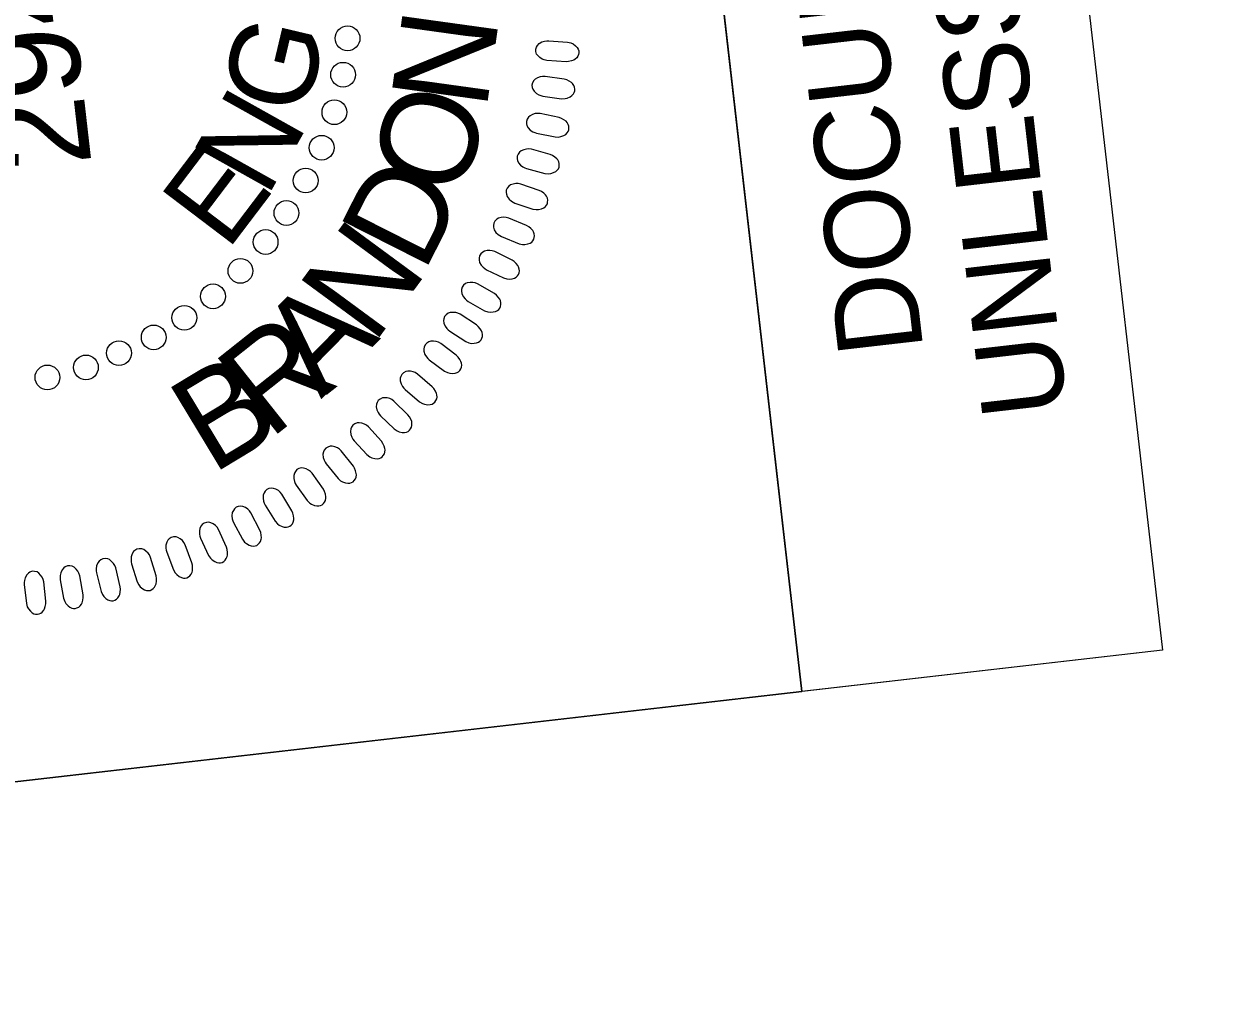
# Model space of a CAD drawing. Extents: x 474105 to 475385, y 502977 to 504774.
# Drawn here: x 474251.2 to 474328.5, y 504432.7 to 504496.5 of the extents above; entities that cross this region are included whole.
import ezdxf

# ---------------------------------------------------------------- set-up
doc = ezdxf.new("R2010")
doc.units = 0
for name, color, linetype in [('Sheet Layout Plan Border', 7, 'Continuous'), ('Sheet PE Seal Cell', 7, 'Continuous'), ('Sheet Plan CELL', 7, 'Continuous'), ('Sheet Sticker Exception Certification CELL', 7, 'Continuous')]:
    doc.layers.add(name, color=color, linetype=linetype)

msp = doc.modelspace()

# ---------------------------------------------------------------- linework, layer by layer
at = {"layer": 'Sheet Layout Plan Border'}
msp.add_lwpolyline([(475344.023, 503264.528), (475192.283, 504585.291), (475112.79, 504576.158), (474903.647, 504485.248), (474306.118, 504619.674), (474302.093, 504654.703), (474324.925, 504455.973), (474152.509, 504436.164), (474168.763, 504438.032), (474279.778, 503999.559), (474242.045, 503987.592), (474254.812, 503913.596), (474216.701, 503877.461), (474300.887, 503144.66)], close=True, dxfattribs=at)
at = {"layer": 'Sheet PE Seal Cell'}
for points in [[(474285.189, 504495.424), (474286.413, 504495.333), (474286.628, 504495.279), (474286.764, 504495.217), (474286.925, 504495.092), (474287.027, 504494.987), (474287.098, 504494.87), (474287.13, 504494.762), (474287.141, 504494.649), (474287.113, 504494.539), (474287.074, 504494.422), (474287.007, 504494.322), (474286.9, 504494.225), (474286.816, 504494.171), (474286.662, 504494.115), (474286.478, 504494.069), (474286.317, 504494.058), (474285.064, 504494.145), (474284.896, 504494.179), (474284.76, 504494.235), (474284.608, 504494.336), (474284.477, 504494.458), (474284.404, 504494.561), (474284.357, 504494.721), (474284.348, 504494.873), (474284.399, 504495.018), (474284.457, 504495.119), (474284.565, 504495.239), (474284.743, 504495.345), (474284.927, 504495.399), (474285.058, 504495.419)], [(474284.808, 504491.836), (474286.024, 504491.667), (474286.245, 504491.675), (474286.392, 504491.707), (474286.575, 504491.795), (474286.697, 504491.876), (474286.791, 504491.977), (474286.845, 504492.074), (474286.88, 504492.183), (474286.875, 504492.296), (474286.862, 504492.42), (474286.818, 504492.531), (474286.733, 504492.648), (474286.663, 504492.719), (474286.523, 504492.805), (474286.353, 504492.889), (474286.198, 504492.933), (474284.955, 504493.113), (474284.784, 504493.114), (474284.639, 504493.088), (474284.469, 504493.021), (474284.315, 504492.93), (474284.223, 504492.844), (474284.142, 504492.697), (474284.102, 504492.552), (474284.121, 504492.397), (474284.157, 504492.287), (474284.238, 504492.148), (474284.389, 504492.006), (474284.558, 504491.915), (474284.682, 504491.868)], [(474284.406, 504489.441), (474285.609, 504489.197), (474285.831, 504489.19), (474285.978, 504489.213), (474286.167, 504489.289), (474286.294, 504489.363), (474286.394, 504489.458), (474286.454, 504489.551), (474286.496, 504489.658), (474286.498, 504489.772), (474286.493, 504489.895), (474286.456, 504490.009), (474286.378, 504490.132), (474286.312, 504490.206), (474286.178, 504490.302), (474286.014, 504490.396), (474285.863, 504490.45), (474284.633, 504490.707), (474284.462, 504490.719), (474284.316, 504490.702), (474284.142, 504490.646), (474283.983, 504490.564), (474283.885, 504490.484), (474283.795, 504490.343), (474283.746, 504490.2), (474283.755, 504490.045), (474283.784, 504489.933), (474283.856, 504489.789), (474283.998, 504489.638), (474284.162, 504489.536), (474284.282, 504489.481)], [(474283.762, 504487.144), (474284.947, 504486.825), (474285.168, 504486.804), (474285.317, 504486.818), (474285.51, 504486.882), (474285.641, 504486.947), (474285.747, 504487.035), (474285.813, 504487.126), (474285.861, 504487.229), (474285.871, 504487.342), (474285.873, 504487.466), (474285.843, 504487.582), (474285.773, 504487.709), (474285.712, 504487.788), (474285.585, 504487.891), (474285.427, 504487.996), (474285.279, 504488.059), (474284.067, 504488.393), (474283.898, 504488.416), (474283.752, 504488.408), (474283.574, 504488.363), (474283.41, 504488.291), (474283.308, 504488.218), (474283.209, 504488.082), (474283.151, 504487.942), (474283.151, 504487.788), (474283.172, 504487.674), (474283.235, 504487.525), (474283.368, 504487.366), (474283.524, 504487.254), (474283.641, 504487.192)], [(474283.003, 504484.915), (474284.165, 504484.523), (474284.385, 504484.488), (474284.534, 504484.492), (474284.731, 504484.544), (474284.866, 504484.601), (474284.977, 504484.682), (474285.049, 504484.768), (474285.103, 504484.869), (474285.12, 504484.981), (474285.13, 504485.104), (474285.107, 504485.222), (474285.046, 504485.353), (474284.99, 504485.436), (474284.87, 504485.547), (474284.719, 504485.662), (474284.575, 504485.734), (474283.387, 504486.143), (474283.218, 504486.176), (474283.072, 504486.177), (474282.892, 504486.144), (474282.724, 504486.083), (474282.617, 504486.016), (474282.51, 504485.886), (474282.443, 504485.751), (474282.433, 504485.597), (474282.447, 504485.481), (474282.501, 504485.329), (474282.623, 504485.162), (474282.772, 504485.041), (474282.885, 504484.971)], [(474282.139, 504482.743), (474283.274, 504482.278), (474283.491, 504482.23), (474283.641, 504482.225), (474283.84, 504482.264), (474283.979, 504482.313), (474284.095, 504482.386), (474284.171, 504482.468), (474284.232, 504482.565), (474284.256, 504482.675), (474284.274, 504482.797), (474284.259, 504482.917), (474284.205, 504483.052), (474284.155, 504483.137), (474284.041, 504483.256), (474283.898, 504483.38), (474283.759, 504483.461), (474282.599, 504483.944), (474282.433, 504483.987), (474282.287, 504483.998), (474282.105, 504483.976), (474281.934, 504483.926), (474281.823, 504483.866), (474281.708, 504483.743), (474281.633, 504483.612), (474281.613, 504483.459), (474281.62, 504483.343), (474281.664, 504483.187), (474281.776, 504483.013), (474281.916, 504482.882), (474282.024, 504482.806)], [(474281.162, 504480.599), (474282.266, 504480.064), (474282.48, 504480.002), (474282.628, 504479.988), (474282.83, 504480.015), (474282.97, 504480.055), (474283.091, 504480.121), (474283.173, 504480.197), (474283.239, 504480.29), (474283.271, 504480.399), (474283.296, 504480.52), (474283.288, 504480.64), (474283.244, 504480.778), (474283.198, 504480.867), (474283.093, 504480.992), (474282.957, 504481.124), (474282.824, 504481.214), (474281.696, 504481.769), (474281.534, 504481.823), (474281.388, 504481.843), (474281.206, 504481.832), (474281.031, 504481.792), (474280.917, 504481.739), (474280.794, 504481.625), (474280.712, 504481.499), (474280.683, 504481.346), (474280.681, 504481.23), (474280.715, 504481.073), (474280.816, 504480.892), (474280.948, 504480.752), (474281.052, 504480.669)], [(474279.975, 504478.549), (474281.043, 504477.945), (474281.252, 504477.87), (474281.4, 504477.847), (474281.603, 504477.861), (474281.746, 504477.892), (474281.871, 504477.95), (474281.957, 504478.021), (474282.03, 504478.109), (474282.067, 504478.217), (474282.1, 504478.336), (474282.1, 504478.456), (474282.064, 504478.597), (474282.024, 504478.688), (474281.926, 504478.82), (474281.8, 504478.96), (474281.672, 504479.058), (474280.582, 504479.683), (474280.423, 504479.747), (474280.279, 504479.776), (474280.097, 504479.777), (474279.919, 504479.748), (474279.803, 504479.703), (474279.673, 504479.596), (474279.582, 504479.475), (474279.543, 504479.325), (474279.536, 504479.209), (474279.559, 504479.05), (474279.649, 504478.863), (474279.772, 504478.715), (474279.87, 504478.625)], [(474278.787, 504476.62), (474279.815, 504475.95), (474280.019, 504475.862), (474280.165, 504475.829), (474280.368, 504475.831), (474280.513, 504475.853), (474280.641, 504475.903), (474280.732, 504475.969), (474280.81, 504476.052), (474280.854, 504476.156), (474280.894, 504476.273), (474280.901, 504476.393), (474280.874, 504476.536), (474280.841, 504476.63), (474280.752, 504476.767), (474280.634, 504476.915), (474280.513, 504477.021), (474279.463, 504477.713), (474279.309, 504477.787), (474279.167, 504477.825), (474278.985, 504477.837), (474278.807, 504477.82), (474278.686, 504477.782), (474278.551, 504477.683), (474278.453, 504477.568), (474278.405, 504477.421), (474278.39, 504477.306), (474278.404, 504477.145), (474278.481, 504476.953), (474278.594, 504476.797), (474278.687, 504476.703)], [(474277.459, 504474.766), (474278.444, 504474.033), (474278.642, 504473.932), (474278.785, 504473.891), (474278.988, 504473.88), (474279.135, 504473.892), (474279.265, 504473.934), (474279.359, 504473.994), (474279.442, 504474.073), (474279.493, 504474.174), (474279.541, 504474.289), (474279.556, 504474.408), (474279.537, 504474.551), (474279.51, 504474.647), (474279.43, 504474.791), (474279.321, 504474.945), (474279.207, 504475.059), (474278.203, 504475.815), (474278.054, 504475.898), (474277.915, 504475.945), (474277.734, 504475.969), (474277.555, 504475.962), (474277.433, 504475.932), (474277.291, 504475.842), (474277.185, 504475.733), (474277.128, 504475.59), (474277.106, 504475.476), (474277.11, 504475.315), (474277.175, 504475.118), (474277.279, 504474.956), (474277.365, 504474.855)], [(474275.891, 504472.839), (474276.827, 504472.046), (474277.018, 504471.933), (474277.159, 504471.882), (474277.361, 504471.858), (474277.507, 504471.862), (474277.641, 504471.896), (474277.739, 504471.95), (474277.826, 504472.022), (474277.884, 504472.121), (474277.938, 504472.232), (474277.96, 504472.35), (474277.951, 504472.494), (474277.929, 504472.591), (474277.859, 504472.74), (474277.76, 504472.901), (474277.654, 504473.021), (474276.699, 504473.839), (474276.555, 504473.932), (474276.419, 504473.987), (474276.24, 504474.023), (474276.061, 504474.027), (474275.938, 504474.004), (474275.79, 504473.924), (474275.678, 504473.822), (474275.612, 504473.682), (474275.583, 504473.57), (474275.576, 504473.409), (474275.629, 504473.208), (474275.722, 504473.04), (474275.802, 504472.934)], [(474274.304, 504471.137), (474275.189, 504470.286), (474275.373, 504470.162), (474275.51, 504470.102), (474275.71, 504470.066), (474275.856, 504470.059), (474275.991, 504470.085), (474276.092, 504470.133), (474276.185, 504470.2), (474276.248, 504470.295), (474276.309, 504470.402), (474276.339, 504470.518), (474276.339, 504470.663), (474276.323, 504470.762), (474276.262, 504470.914), (474276.174, 504471.081), (474276.075, 504471.208), (474275.173, 504472.085), (474275.036, 504472.186), (474274.904, 504472.25), (474274.727, 504472.295), (474274.548, 504472.312), (474274.424, 504472.297), (474274.272, 504472.225), (474274.154, 504472.131), (474274.079, 504471.996), (474274.043, 504471.886), (474274.026, 504471.725), (474274.065, 504471.522), (474274.148, 504471.348), (474274.221, 504471.237)], [(474272.595, 504469.528), (474273.425, 504468.623), (474273.601, 504468.487), (474273.733, 504468.419), (474273.931, 504468.37), (474274.077, 504468.355), (474274.213, 504468.373), (474274.317, 504468.414), (474274.414, 504468.475), (474274.482, 504468.565), (474274.55, 504468.668), (474274.587, 504468.783), (474274.597, 504468.927), (474274.587, 504469.027), (474274.535, 504469.182), (474274.458, 504469.355), (474274.367, 504469.488), (474273.523, 504470.418), (474273.391, 504470.528), (474273.264, 504470.601), (474273.09, 504470.658), (474272.914, 504470.685), (474272.788, 504470.678), (474272.631, 504470.616), (474272.508, 504470.529), (474272.425, 504470.399), (474272.381, 504470.292), (474272.355, 504470.132), (474272.382, 504469.927), (474272.453, 504469.748), (474272.519, 504469.633)], [(474270.779, 504468.034), (474271.55, 504467.08), (474271.717, 504466.932), (474271.845, 504466.857), (474272.039, 504466.795), (474272.183, 504466.771), (474272.321, 504466.779), (474272.427, 504466.814), (474272.527, 504466.869), (474272.602, 504466.956), (474272.676, 504467.054), (474272.72, 504467.166), (474272.739, 504467.309), (474272.735, 504467.409), (474272.693, 504467.568), (474272.627, 504467.745), (474272.544, 504467.883), (474271.76, 504468.865), (474271.637, 504468.983), (474271.513, 504469.063), (474271.344, 504469.131), (474271.169, 504469.169), (474271.043, 504469.17), (474270.883, 504469.118), (474270.754, 504469.039), (474270.663, 504468.915), (474270.613, 504468.81), (474270.577, 504468.652), (474270.59, 504468.446), (474270.651, 504468.263), (474270.709, 504468.144)], [(474268.85, 504466.649), (474269.56, 504465.647), (474269.717, 504465.491), (474269.84, 504465.407), (474270.029, 504465.333), (474270.173, 504465.3), (474270.31, 504465.3), (474270.418, 504465.327), (474270.522, 504465.376), (474270.601, 504465.457), (474270.681, 504465.551), (474270.732, 504465.66), (474270.76, 504465.802), (474270.763, 504465.902), (474270.731, 504466.063), (474270.676, 504466.244), (474270.603, 504466.387), (474269.882, 504467.417), (474269.765, 504467.542), (474269.647, 504467.629), (474269.482, 504467.708), (474269.31, 504467.757), (474269.184, 504467.766), (474269.022, 504467.724), (474268.888, 504467.653), (474268.79, 504467.534), (474268.733, 504467.433), (474268.687, 504467.279), (474268.688, 504467.071), (474268.736, 504466.885), (474268.787, 504466.763)], [(474266.835, 504465.363), (474267.48, 504464.319), (474267.627, 504464.152), (474267.745, 504464.061), (474267.93, 504463.976), (474268.07, 504463.934), (474268.208, 504463.925), (474268.317, 504463.946), (474268.423, 504463.988), (474268.508, 504464.064), (474268.594, 504464.153), (474268.652, 504464.258), (474268.688, 504464.398), (474268.697, 504464.497), (474268.676, 504464.66), (474268.632, 504464.844), (474268.567, 504464.992), (474267.913, 504466.065), (474267.804, 504466.197), (474267.693, 504466.292), (474267.533, 504466.38), (474267.364, 504466.441), (474267.239, 504466.457), (474267.074, 504466.425), (474266.936, 504466.364), (474266.831, 504466.251), (474266.767, 504466.153), (474266.712, 504466.002), (474266.7, 504465.795), (474266.736, 504465.607), (474266.779, 504465.481)], [(474264.792, 504464.223), (474265.37, 504463.141), (474265.507, 504462.965), (474265.619, 504462.866), (474265.798, 504462.769), (474265.936, 504462.718), (474266.072, 504462.701), (474266.182, 504462.715), (474266.291, 504462.75), (474266.38, 504462.821), (474266.472, 504462.904), (474266.536, 504463.005), (474266.581, 504463.143), (474266.596, 504463.242), (474266.585, 504463.406), (474266.553, 504463.592), (474266.498, 504463.743), (474265.912, 504464.855), (474265.812, 504464.994), (474265.707, 504465.096), (474265.553, 504465.194), (474265.388, 504465.264), (474265.264, 504465.289), (474265.097, 504465.268), (474264.956, 504465.215), (474264.844, 504465.109), (474264.775, 504465.016), (474264.709, 504464.868), (474264.685, 504464.662), (474264.709, 504464.472), (474264.745, 504464.344)], [(474262.656, 504463.213), (474263.166, 504462.098), (474263.291, 504461.914), (474263.396, 504461.808), (474263.569, 504461.7), (474263.703, 504461.641), (474263.838, 504461.615), (474263.949, 504461.622), (474264.06, 504461.65), (474264.153, 504461.715), (474264.25, 504461.792), (474264.32, 504461.89), (474264.373, 504462.024), (474264.396, 504462.121), (474264.394, 504462.285), (474264.374, 504462.474), (474264.328, 504462.628), (474263.813, 504463.774), (474263.722, 504463.919), (474263.623, 504464.028), (474263.476, 504464.135), (474263.316, 504464.216), (474263.194, 504464.248), (474263.027, 504464.237), (474262.882, 504464.193), (474262.763, 504464.095), (474262.688, 504464.006), (474262.614, 504463.863), (474262.576, 504463.659), (474262.589, 504463.468), (474262.616, 504463.337)], [(474260.462, 504462.303), (474260.9, 504461.157), (474261.014, 504460.966), (474261.112, 504460.854), (474261.277, 504460.736), (474261.408, 504460.668), (474261.541, 504460.634), (474261.653, 504460.634), (474261.765, 504460.655), (474261.862, 504460.714), (474261.963, 504460.785), (474262.039, 504460.877), (474262.101, 504461.009), (474262.129, 504461.104), (474262.138, 504461.268), (474262.13, 504461.457), (474262.094, 504461.614), (474261.652, 504462.791), (474261.571, 504462.941), (474261.479, 504463.055), (474261.338, 504463.172), (474261.183, 504463.262), (474261.065, 504463.302), (474260.896, 504463.302), (474260.749, 504463.267), (474260.624, 504463.176), (474260.544, 504463.092), (474260.46, 504462.954), (474260.41, 504462.753), (474260.411, 504462.561), (474260.43, 504462.429)], [(474258.191, 504461.56), (474258.556, 504460.388), (474258.657, 504460.19), (474258.748, 504460.072), (474258.907, 504459.944), (474259.032, 504459.868), (474259.163, 504459.826), (474259.274, 504459.819), (474259.387, 504459.833), (474259.488, 504459.885), (474259.593, 504459.95), (474259.676, 504460.038), (474259.746, 504460.164), (474259.779, 504460.258), (474259.799, 504460.421), (474259.803, 504460.611), (474259.777, 504460.769), (474259.409, 504461.971), (474259.337, 504462.126), (474259.253, 504462.246), (474259.12, 504462.371), (474258.971, 504462.472), (474258.854, 504462.519), (474258.687, 504462.529), (474258.538, 504462.503), (474258.407, 504462.421), (474258.322, 504462.342), (474258.231, 504462.209), (474258.167, 504462.012), (474258.156, 504461.82), (474258.167, 504461.688)], [(474253.572, 504460.528), (474253.788, 504459.32), (474253.863, 504459.111), (474253.939, 504458.982), (474254.079, 504458.835), (474254.194, 504458.744), (474254.319, 504458.685), (474254.429, 504458.664), (474254.543, 504458.665), (474254.649, 504458.704), (474254.762, 504458.755), (474254.855, 504458.831), (474254.94, 504458.948), (474254.985, 504459.037), (474255.024, 504459.196), (474255.052, 504459.384), (474255.046, 504459.544), (474254.832, 504460.783), (474254.78, 504460.946), (474254.711, 504461.075), (474254.595, 504461.217), (474254.46, 504461.334), (474254.351, 504461.396), (474254.186, 504461.428), (474254.035, 504461.421), (474253.895, 504461.355), (474253.8, 504461.287), (474253.693, 504461.167), (474253.605, 504460.979), (474253.57, 504460.79), (474253.564, 504460.657)], [(474255.919, 504460.963), (474256.21, 504459.771), (474256.298, 504459.567), (474256.382, 504459.444), (474256.531, 504459.306), (474256.652, 504459.222), (474256.78, 504459.171), (474256.891, 504459.158), (474257.005, 504459.165), (474257.108, 504459.211), (474257.218, 504459.268), (474257.306, 504459.351), (474257.383, 504459.473), (474257.423, 504459.565), (474257.452, 504459.725), (474257.468, 504459.915), (474257.452, 504460.075), (474257.161, 504461.297), (474257.099, 504461.456), (474257.021, 504461.581), (474256.897, 504461.715), (474256.755, 504461.824), (474256.642, 504461.879), (474256.475, 504461.9), (474256.325, 504461.883), (474256.189, 504461.809), (474256.099, 504461.736), (474255.999, 504461.609), (474255.924, 504461.416), (474255.901, 504461.225), (474255.903, 504461.092)], [(474251.236, 504460.206), (474251.375, 504458.988), (474251.438, 504458.774), (474251.505, 504458.641), (474251.636, 504458.485), (474251.745, 504458.387), (474251.866, 504458.321), (474251.974, 504458.293), (474252.088, 504458.286), (474252.196, 504458.319), (474252.312, 504458.362), (474252.409, 504458.433), (474252.502, 504458.545), (474252.552, 504458.63), (474252.602, 504458.787), (474252.641, 504458.972), (474252.645, 504459.133), (474252.51, 504460.383), (474252.468, 504460.548), (474252.407, 504460.682), (474252.3, 504460.83), (474252.173, 504460.956), (474252.067, 504461.025), (474251.905, 504461.066), (474251.754, 504461.069), (474251.61, 504461.012), (474251.512, 504460.95), (474251.396, 504460.837), (474251.297, 504460.655), (474251.251, 504460.469), (474251.236, 504460.337)]]:
    msp.add_lwpolyline(points, close=True, dxfattribs=at)
for centre in [(474272.17, 504495.581), (474271.879, 504493.223), (474271.315, 504490.794), (474270.495, 504488.496), (474269.455, 504486.373), (474268.213, 504484.268), (474266.864, 504482.39), (474265.234, 504480.52), (474263.458, 504478.874), (474261.6, 504477.484), (474259.621, 504476.215), (474257.372, 504475.196), (474255.232, 504474.27), (474252.74, 504473.624)]:
    msp.add_circle(centre, 0.801, dxfattribs=at)
at = {"layer": 'Sheet Plan CELL'}
for points in [[(475344.023, 503264.528), (474300.912, 503144.663), (474152.498, 504436.15), (474301.579, 504453.291), (474278.759, 504652.022), (475172.816, 504754.738)], [(474189.828, 504440.439), (474178.408, 504539.835), (474290.186, 504552.677), (474301.579, 504453.291)]]:
    msp.add_lwpolyline(points, close=True, dxfattribs=at)
at = {"layer": 'Sheet Sticker Exception Certification CELL'}
for p, q in [((474302.093, 504654.703), (474324.925, 504455.973)), ((474302.093, 504654.703), (474324.925, 504455.973)), ((474301.579, 504453.291), (474278.747, 504652.021)), ((474301.579, 504453.291), (474278.747, 504652.021)), ((474324.925, 504455.973), (474301.579, 504453.291)), ((474324.925, 504455.973), (474301.579, 504453.291))]:
    msp.add_line(p, q, dxfattribs=at)

# ---------------------------------------------------------------- texts
at = {"layer": 'Sheet PE Seal Cell'}
for s, height, rotation, p in [('29470', 6.2363, 96.5352, (474255.606, 504487.417)), ('N', 6.236, 82.10435, (474281.151, 504490.866)), ('G', 5.669, 76.63882, (474269.468, 504490.418)), ('N', 5.669, 60.75922, (474266.948, 504485.202)), ('O', 6.236, 72.0045, (474279.429, 504485.08)), ('E', 5.669, 52.81943, (474264.37, 504481.75)), ('D', 6.236, 63.13627, (474277.099, 504480.316)), ('N', 6.236, 53.64658, (474273.826, 504475.683)), ('A', 6.236, 45.53541, (474270.454, 504472.196)), ('R', 6.236, 38.41857, (474267.115, 504469.555)), ('B', 6.236, 31.14354, (474263.391, 504467.304))]:
    msp.add_text(s, height=height, rotation=rotation, dxfattribs=at).set_placement(p)
at = {"layer": 'Sheet Sticker Exception Certification CELL'}
for s, p in [('UNLESS ALL SIGNATURES COMPLETED', (474318.773, 504471.371)), ('UNLESS ALL SIGNATURES COMPLETED', (474318.773, 504471.371)), ('DOCUMENT NOT CONSIDERED FINAL', (474309.452, 504475.405)), ('DOCUMENT NOT CONSIDERED FINAL', (474309.452, 504475.405))]:
    msp.add_text(s, height=5.5, rotation=96.55384, dxfattribs=at).set_placement(p)

doc.saveas('drawing.dxf')
